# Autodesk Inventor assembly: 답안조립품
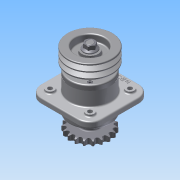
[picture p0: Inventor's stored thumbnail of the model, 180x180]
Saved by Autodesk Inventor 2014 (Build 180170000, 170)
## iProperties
Created: 2015-09
Part Number: 답안조립품
Document SubType Name: Assembly
Designer: study
Author: study
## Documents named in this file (12)
- C:\Users\study\Desktop\450909V1003\답안조립품.iam
- C:\Users\study\Desktop\450909V1003\1-본체.ipt
- C:\Users\study\Desktop\450909V1003\6-베어링 6206.ipt
- C:\Users\study\Desktop\450909V1003\8-오일실 30x42.ipt
- C:\Users\study\Desktop\450909V1003\2-커버.ipt
- C:\Users\study\Desktop\450909V1003\3-축.ipt
- C:\Users\study\Desktop\450909V1003\11-키 6x6.ipt
- C:\Users\study\Desktop\450909V1003\10-M6.ipt
- C:\Users\study\Desktop\450909V1003\4-V벨트풀리.ipt
- C:\Users\study\Desktop\450909V1003\5-체인 스프로킷.ipt
- C:\Users\study\Desktop\450909V1003\7-부시.ipt
- C:\Users\study\Desktop\450909V1003\9-M16-너트.ipt
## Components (23 placed, 11 different names)
1. 1-본체:1 — 각도:5, 각도:6
2. 6-베어링 6206:1
3. 6-베어링 6206:2
4. 8-8-오일실 30x42:1
5. 8-8-오일실 30x42:2
6. 2-커버:1
7. 2-커버:2
8. 3-축:1 — 각도:1, 각도:2
9. 11-키 6x6:1 — 각도:2, 각도:4
10. 11-키 6x6:2 — 각도:1, 각도:3
11. 4-V벨트풀리:1 — 각도:3
12. 5-체인 스프로킷:1 — 각도:4
13. 7-부시:1
14. 9-M16 너트:1 — 각도:5
15. 9-M16 너트:2 — 각도:6
16. 10-M6:2
17. 10-M6:3
18. 10-M6:4
19. 10-M6:5
20. 10-M6:1
21. 10-M6:6
22. 10-M6:7
23. 10-M6:8
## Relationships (6: Angle 6)
- 각도:1 [Angle]: 3-축:1 ↔ 11-키 6x6:2
- 각도:2 [Angle]: 3-축:1 ↔ 11-키 6x6:1
- 각도:3 [Angle]: 11-키 6x6:2 ↔ 4-V벨트풀리:1
- 각도:4 [Angle]: 11-키 6x6:1 ↔ 5-체인 스프로킷:1
- 각도:5 [Angle]: 1-본체:1 ↔ 9-M16 너트:1
- 각도:6 [Angle]: 1-본체:1 ↔ 9-M16 너트:2
